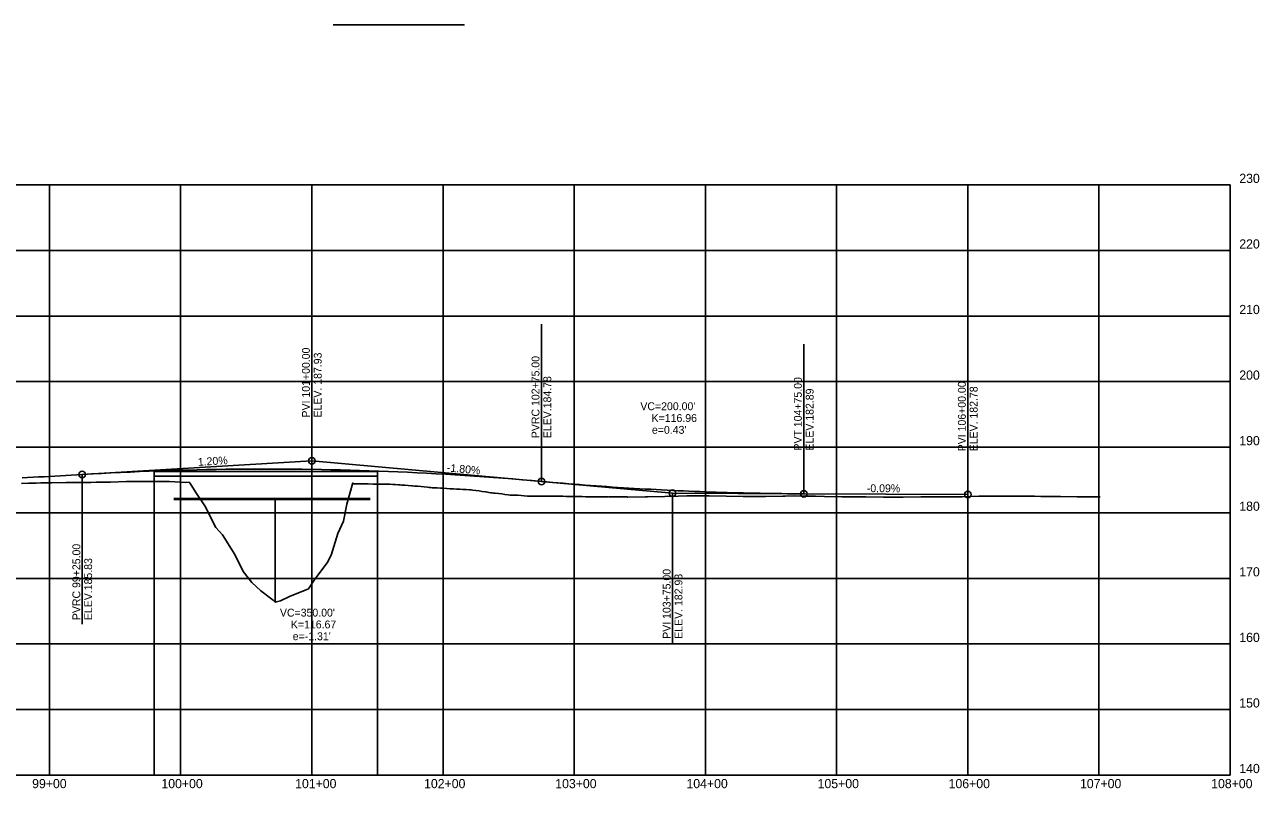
# Model space of a CAD drawing. Extents: x 1 to 1477871, y 1 to 1872901.
# Drawn here: x 1445940 to 1446881, y 1853296 to 1853878 of the extents above; entities that cross this region are included whole.
import ezdxf

# ---------------------------------------------------------------- set-up
doc = ezdxf.new("R2010")
doc.units = 0
for name, color, linetype in [('R_Axis', 7, 'Continuous'), ('R_Axis Annot', 7, 'Continuous'), ('R_Exist Surface', 7, 'Continuous'), ('R_Grid', 7, 'Continuous'), ('R_No Plot', 7, 'Continuous'), ('R_Vert Alg', 7, 'Continuous'), ('R_Vert Alg Annot', 7, 'Continuous'), ('R_Water', 7, 'Continuous')]:
    doc.layers.add(name, color=color, linetype=linetype)

msp = doc.modelspace()

# ---------------------------------------------------------------- linework, layer by layer
at = {"layer": 'R_Axis'}
for p, q in [((1446859.14, 1853306), (1446859.14, 1853756)), ((1444759.14, 1853306), (1446859.14, 1853306))]:
    msp.add_line(p, q, dxfattribs=at)
at = {"layer": 'R_Exist Surface'}
msp.add_lwpolyline([(1445937.76, 1853528.4), (1445943.06, 1853528.52), (1445945.2, 1853528.63), (1445945.75, 1853528.65), (1445949.03, 1853528.69), (1445952.64, 1853528.71), (1445960.71, 1853528.75), (1445971.93, 1853529.03), (1445975.74, 1853529.09), (1445978.15, 1853529.16), (1445990.7, 1853529.13), (1445994.67, 1853529.23), (1446005.66, 1853529.3), (1446017.56, 1853529.85), (1446020.7, 1853529.88), (1446022.94, 1853529.95), (1446035.71, 1853529.89), (1446038.25, 1853529.89), (1446050.72, 1853529.83), (1446063.12, 1853529.19), (1446065.72, 1853529.23), (1446065.79, 1853529.17), (1446066.15, 1853528.95), (1446070.79, 1853521.49), (1446077.6, 1853511.42), (1446085.88, 1853494.67), (1446091.14, 1853489.15), (1446100.42, 1853474.19), (1446106.69, 1853461.12), (1446113.31, 1853452.75), (1446120.38, 1853446.49), (1446129.66, 1853439.34), (1446131.21, 1853437.77), (1446135.25, 1853438.95), (1446142.19, 1853442.04), (1446156.54, 1853447.98), (1446161.42, 1853455.43), (1446170.73, 1853467.79), (1446173.88, 1853473.72), (1446178.98, 1853490.29), (1446183.34, 1853499.49), (1446185.7, 1853512.46), (1446190.51, 1853528.76), (1446190.95, 1853528.35), (1446191.08, 1853528.16), (1446202.11, 1853528.09), (1446205.89, 1853527.89), (1446218.51, 1853527.72), (1446220.9, 1853527.54), (1446222.76, 1853527.44), (1446225.22, 1853527.3), (1446226.54, 1853527.23), (1446227.68, 1853527.14), (1446230.14, 1853526.96), (1446232.59, 1853526.78), (1446235.05, 1853526.59), (1446235.82, 1853526.53), (1446237.51, 1853526.39), (1446239.97, 1853526.17), (1446242.42, 1853525.96), (1446244.88, 1853525.74), (1446247.34, 1853525.52), (1446248.6, 1853525.4), (1446249.8, 1853525.26), (1446250.8, 1853525.14), (1446251.91, 1853525.12), (1446252.25, 1853525.1), (1446254.71, 1853524.96), (1446257.17, 1853524.82), (1446259.62, 1853524.67), (1446262.08, 1853524.52), (1446264.54, 1853524.37), (1446265.79, 1853524.29), (1446267, 1853524.17), (1446267.05, 1853524.16), (1446269.45, 1853524.04), (1446271.91, 1853523.91), (1446274.37, 1853523.78), (1446276.83, 1853523.63), (1446279.28, 1853523.47), (1446280.63, 1853523.38), (1446281.74, 1853523.25), (1446284.2, 1853522.96), (1446286.66, 1853522.65), (1446289.11, 1853522.34), (1446291.57, 1853522.02), (1446291.94, 1853521.97), (1446294.03, 1853521.56), (1446295.51, 1853521.26), (1446296.49, 1853521.12), (1446297.61, 1853520.96), (1446298.94, 1853520.83), (1446301.4, 1853520.59), (1446303.86, 1853520.32), (1446306.31, 1853520.04), (1446308.77, 1853519.74), (1446310.34, 1853519.54), (1446311.23, 1853519.53), (1446313.69, 1853519.45), (1446314.98, 1853519.41), (1446316.14, 1853519.33), (1446318.6, 1853519.16), (1446321.06, 1853518.98), (1446323.52, 1853518.78), (1446325.16, 1853518.64), (1446325.97, 1853518.66), (1446328.43, 1853518.69), (1446330.89, 1853518.71), (1446333.35, 1853518.71), (1446335.8, 1853518.71), (1446338.26, 1853518.69), (1446338.41, 1853518.69), (1446340.03, 1853518.63), (1446340.72, 1853518.68), (1446341.23, 1853518.71), (1446343.18, 1853518.69), (1446345.63, 1853518.66), (1446348.09, 1853518.61), (1446350.55, 1853518.56), (1446353, 1853518.5), (1446355.01, 1853518.44), (1446355.46, 1853518.44), (1446357.92, 1853518.42), (1446360.38, 1853518.39), (1446360.72, 1853518.38), (1446362.83, 1853518.34), (1446365.29, 1853518.29), (1446367.75, 1853518.24), (1446369.81, 1853518.19), (1446369.97, 1853518.19), (1446369.98, 1853518.19), (1446369.99, 1853518.19), (1446370.04, 1853518.19), (1446370.21, 1853518.19), (1446372.66, 1853518.16), (1446375.12, 1853518.14), (1446377.58, 1853518.12), (1446380.04, 1853518.09), (1446382.49, 1853518.07), (1446384.71, 1853518.05), (1446384.95, 1853518.03), (1446384.98, 1853518.03), (1446385.32, 1853518.04), (1446387.41, 1853518.04), (1446389.86, 1853518.04), (1446392.32, 1853518.05), (1446394.38, 1853518.06), (1446394.78, 1853518.06), (1446397.24, 1853518.05), (1446399.21, 1853518.04), (1446399.69, 1853518.03), (1446400, 1853518.03), (1446413.47, 1853518.22), (1446415.02, 1853518.28), (1446428.22, 1853518.49), (1446429.94, 1853518.56), (1446431.8, 1853518.53), (1446444.96, 1853518.86), (1446446.99, 1853518.86), (1446459.94, 1853518.91), (1446462.02, 1853518.91), (1446474.95, 1853518.72), (1446488.03, 1853518.41), (1446489.93, 1853518.43), (1446503.24, 1853518.35), (1446504.94, 1853518.31), (1446518.31, 1853518.68), (1446519.95, 1853518.61), (1446527.06, 1853518.82), (1446534.94, 1853518.68), (1446543.09, 1853518.64), (1446549.95, 1853518.36), (1446563.15, 1853518.21), (1446564.95, 1853518.2), (1446578.18, 1853518.19), (1446579.95, 1853518.19), (1446581.54, 1853518.21), (1446594.96, 1853517.99), (1446608.3, 1853518.01), (1446609.96, 1853518.01), (1446623.27, 1853518.15), (1446624.96, 1853518.13), (1446638.21, 1853518.21), (1446639.96, 1853518.21), (1446642.03, 1853518.26), (1446654.98, 1853518.25), (1446667.65, 1853518.64), (1446669.96, 1853518.64), (1446672.04, 1853518.64), (1446684.98, 1853518.66), (1446689.75, 1853518.71), (1446699.96, 1853518.7), (1446709.94, 1853518.56), (1446714.96, 1853518.39), (1446717.28, 1853518.44), (1446729.95, 1853518.4), (1446742.65, 1853518.13), (1446744.98, 1853518.08), (1446751.01, 1853518.25), (1446759.96, 1853518.21)], dxfattribs=at)
at = {"layer": 'R_Grid'}
for p, q in [((1444759.14, 1853756), (1446859.14, 1853756)), ((1444759.14, 1853756), (1446859.14, 1853756)), ((1445959.14, 1853306), (1445959.14, 1853756)), ((1446059.14, 1853306), (1446059.14, 1853756)), ((1446159.14, 1853306), (1446159.14, 1853756)), ((1446259.14, 1853306), (1446259.14, 1853756)), ((1446359.14, 1853306), (1446359.14, 1853756)), ((1446459.14, 1853306), (1446459.14, 1853756)), ((1446559.14, 1853306), (1446559.14, 1853756)), ((1446659.14, 1853306), (1446659.14, 1853756)), ((1446759.14, 1853306), (1446759.14, 1853756)), ((1444759.14, 1853706), (1446859.14, 1853706)), ((1444759.14, 1853656), (1446859.14, 1853656)), ((1444759.14, 1853606), (1446859.14, 1853606)), ((1444759.14, 1853556), (1446859.14, 1853556)), ((1444759.14, 1853506), (1446859.14, 1853506)), ((1444759.14, 1853456), (1446859.14, 1853456)), ((1444759.14, 1853406), (1446859.14, 1853406)), ((1444759.14, 1853356), (1446859.14, 1853356))]:
    msp.add_line(p, q, dxfattribs=at)
at = {"layer": 'R_No Plot'}
for p, q in [((1446038.95, 1853537.56), (1446209.33, 1853537.56)), ((1446038.95, 1853306), (1446038.95, 1853537.56)), ((1446209.33, 1853306), (1446209.33, 1853537.56)), ((1446038.95, 1853533.81), (1446209.33, 1853533.81)), ((1446053.94, 1853516.89), (1446203.69, 1853516.89)), ((1446053.94, 1853516.15), (1446203.69, 1853516.15)), ((1446131.21, 1853437.77), (1446131.21, 1853516.15))]:
    msp.add_line(p, q, dxfattribs=at)
at = {"layer": 'R_Vert Alg'}
for p, q in [((1445983.79, 1853535.12), (1446159.14, 1853545.65)), ((1446159.14, 1853545.65), (1446334.14, 1853529.9)), ((1446334.14, 1853529.9), (1446434.14, 1853520.9)), ((1446434.14, 1853520.9), (1446534.14, 1853520.45)), ((1446534.14, 1853520.45), (1446659.14, 1853519.88))]:
    msp.add_line(p, q, dxfattribs=at)
for points in [[(1445984.14, 1853535.15), (1445991.44, 1853535.57), (1445998.73, 1853535.98), (1446006.02, 1853536.36), (1446013.31, 1853536.71), (1446020.6, 1853537.05), (1446027.89, 1853537.36), (1446035.19, 1853537.65), (1446042.48, 1853537.92), (1446049.77, 1853538.16), (1446057.06, 1853538.38), (1446064.35, 1853538.58), (1446071.64, 1853538.76), (1446078.94, 1853538.91), (1446086.23, 1853539.04), (1446093.52, 1853539.15), (1446100.81, 1853539.23), (1446108.1, 1853539.29), (1446115.39, 1853539.33), (1446122.69, 1853539.35), (1446129.98, 1853539.34), (1446137.27, 1853539.31), (1446144.56, 1853539.26), (1446151.85, 1853539.18), (1446166.44, 1853538.96), (1446173.73, 1853538.82), (1446181.02, 1853538.65), (1446188.31, 1853538.46), (1446195.6, 1853538.25), (1446202.89, 1853538.02), (1446210.19, 1853537.76), (1446217.48, 1853537.48), (1446224.77, 1853537.18), (1446232.06, 1853536.85), (1446239.35, 1853536.5), (1446246.64, 1853536.13), (1446253.94, 1853535.74), (1446261.23, 1853535.32), (1446268.52, 1853534.88), (1446275.81, 1853534.42), (1446283.1, 1853533.93), (1446290.39, 1853533.42), (1446297.69, 1853532.89), (1446304.98, 1853532.34), (1446312.27, 1853531.76), (1446319.56, 1853531.16), (1446326.85, 1853530.54), (1446334.14, 1853529.9)], [(1445938.31, 1853532.66), (1445942.48, 1853532.86), (1445946.64, 1853533.07), (1445950.81, 1853533.29), (1445954.98, 1853533.5), (1445959.14, 1853533.72), (1445963.31, 1853533.95), (1445967.48, 1853534.18), (1445971.64, 1853534.42), (1445975.81, 1853534.65), (1445979.98, 1853534.9), (1445984.14, 1853535.15)], [(1446334.14, 1853529.9), (1446338.31, 1853529.52), (1446342.48, 1853529.16), (1446346.64, 1853528.8), (1446350.81, 1853528.46), (1446354.98, 1853528.11), (1446359.14, 1853527.78), (1446363.31, 1853527.45), (1446367.48, 1853527.13), (1446371.64, 1853526.82), (1446375.81, 1853526.52), (1446379.98, 1853526.22), (1446384.14, 1853525.93), (1446388.31, 1853525.65), (1446392.48, 1853525.37), (1446396.64, 1853525.11), (1446400.81, 1853524.85), (1446404.98, 1853524.59), (1446409.14, 1853524.35), (1446413.31, 1853524.11), (1446417.48, 1853523.88), (1446421.64, 1853523.66), (1446425.81, 1853523.44), (1446429.98, 1853523.23), (1446438.31, 1853522.84), (1446442.48, 1853522.65), (1446446.64, 1853522.48), (1446450.81, 1853522.31), (1446454.98, 1853522.14), (1446459.14, 1853521.99), (1446463.31, 1853521.84), (1446467.48, 1853521.7), (1446471.64, 1853521.56), (1446475.81, 1853521.44), (1446479.98, 1853521.32), (1446484.14, 1853521.21), (1446488.31, 1853521.1), (1446492.48, 1853521), (1446496.64, 1853520.92), (1446500.81, 1853520.83), (1446504.98, 1853520.76), (1446509.14, 1853520.69), (1446513.31, 1853520.63), (1446517.48, 1853520.58), (1446521.64, 1853520.54), (1446525.81, 1853520.5), (1446529.98, 1853520.47), (1446534.14, 1853520.45)]]:
    msp.add_lwpolyline(points, dxfattribs=at)
at = {"layer": 'R_Vert Alg Annot'}
for p, q in [((1446159.14, 1853575.65), (1446159.14, 1853659.65)), ((1446334.14, 1853559.9), (1446334.14, 1853649.9)), ((1446534.14, 1853550.45), (1446534.14, 1853634.45)), ((1446659.14, 1853549.88), (1446659.14, 1853633.88)), ((1446159.14, 1853545.65), (1446159.14, 1853575.65)), ((1446334.14, 1853529.9), (1446334.14, 1853559.9)), ((1446534.14, 1853520.45), (1446534.14, 1853550.45)), ((1446659.14, 1853519.88), (1446659.14, 1853549.88)), ((1445984.14, 1853535.15), (1445984.14, 1853505.15)), ((1446434.14, 1853520.9), (1446434.14, 1853490.9)), ((1445984.14, 1853505.15), (1445984.14, 1853421.15)), ((1446434.14, 1853490.9), (1446434.14, 1853406.9))]:
    msp.add_line(p, q, dxfattribs=at)
for centre in [(1446159.14, 1853545.65), (1445984.14, 1853535.15), (1446334.14, 1853529.9), (1446434.14, 1853520.9), (1446534.14, 1853520.45), (1446659.14, 1853519.88)]:
    msp.add_circle(centre, 2.5, dxfattribs=at)
at = {"layer": 'R_Water'}
for q in [(1446175.33, 1853878.18), (1446275.33, 1853877.73)]:
    msp.add_line((1446275.33, 1853878.18), q, dxfattribs=at)

# ---------------------------------------------------------------- texts
at = {"layer": 'R_Axis Annot'}
for s, p in [('230', (1446866.14, 1853757.5)), ('230', (1446866.14, 1853757.5)), ('220', (1446866.14, 1853707.5)), ('210', (1446866.14, 1853657.5)), ('200', (1446866.14, 1853607.5)), ('190', (1446866.14, 1853557.5)), ('180', (1446866.14, 1853507.5)), ('170', (1446866.14, 1853457.5)), ('160', (1446866.14, 1853407.5)), ('150', (1446866.14, 1853357.5)), ('140', (1446866.14, 1853307.5)), ('99+00', (1445945.94, 1853296)), ('100+00', (1446044.48, 1853296)), ('101+00', (1446146.41, 1853296)), ('102+00', (1446244.71, 1853296)), ('103+00', (1446344.71, 1853296)), ('104+00', (1446444.71, 1853296)), ('105+00', (1446544.71, 1853296)), ('106+00', (1446644.57, 1853296)), ('107+00', (1446744.71, 1853296)), ('108+00', (1446844.71, 1853296))]:
    msp.add_text(s, height=7, dxfattribs=at).set_placement(p)
at = {"layer": 'R_Vert Alg Annot'}
for s, rotation, p in [('PVI 101+00.00', 90, (1446157.64, 1853578.65)), ('ELEV. 187.93', 90, (1446166.64, 1853578.65)), ('PVRC 102+75.00', 90, (1446332.64, 1853562.9)), ('ELEV.184.78', 90, (1446341.64, 1853562.9)), ('PVT 104+75.00', 90, (1446532.64, 1853553.45)), ('PVI 106+00.00', 90, (1446657.64, 1853552.88)), ('ELEV.182.89', 90, (1446541.64, 1853553.45)), ('ELEV. 182.78', 90, (1446666.64, 1853552.88)), ('1.20%', 3.43363, (1446072.41, 1853541.75)), ('-1.80%', 354.85724, (1446261.98, 1853537.51)), ('-0.09%', 359.74217, (1446582.22, 1853521.73)), ('PVRC 99+25.00', 90, (1445982.64, 1853424.15)), ('ELEV.185.83', 90, (1445991.64, 1853424.15)), ('PVI 103+75.00', 90, (1446432.64, 1853409.9)), ('ELEV. 182.98', 90, (1446441.64, 1853409.9))]:
    msp.add_text(s, height=6, rotation=rotation, dxfattribs=at).set_placement(p)
for s, p in [("VC=200.00'", (1446409.58, 1853584.24)), ('K=116.96', (1446418.15, 1853575.24)), ("e=0.43'", (1446418.41, 1853566.24)), ("VC=350.00'", (1446134.81, 1853426.85)), ('K=116.67', (1446143.18, 1853417.85)), ("e=-1.31'", (1446144.59, 1853408.85))]:
    msp.add_text(s, height=6, dxfattribs=at).set_placement(p)

doc.saveas('drawing.dxf')
